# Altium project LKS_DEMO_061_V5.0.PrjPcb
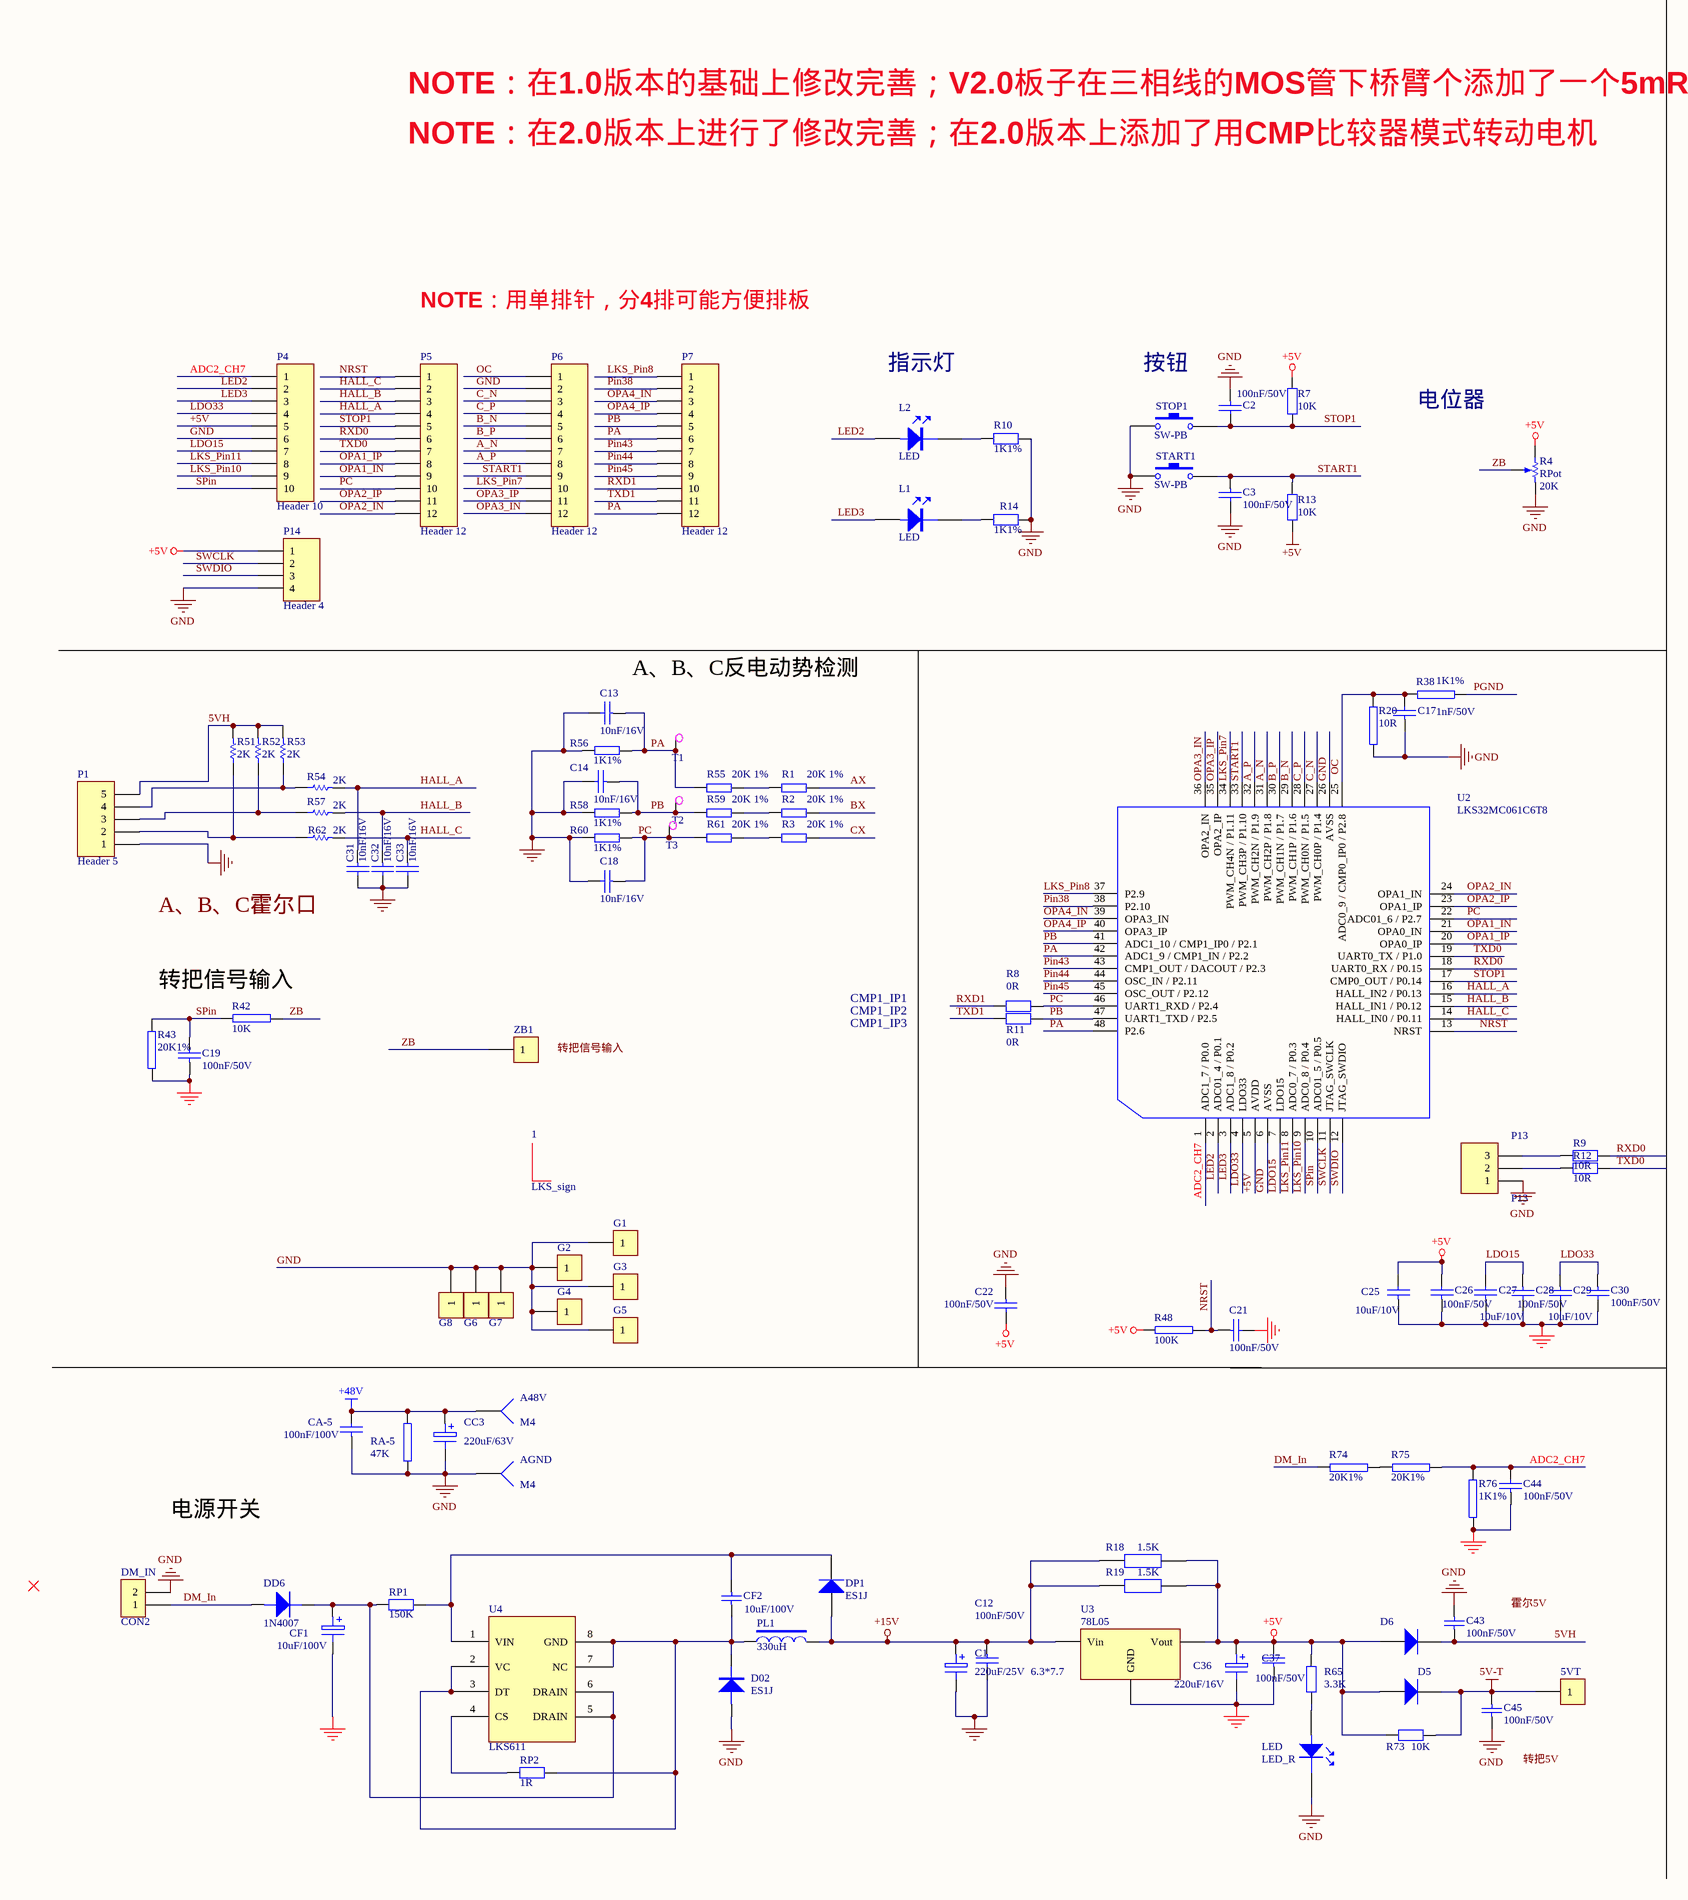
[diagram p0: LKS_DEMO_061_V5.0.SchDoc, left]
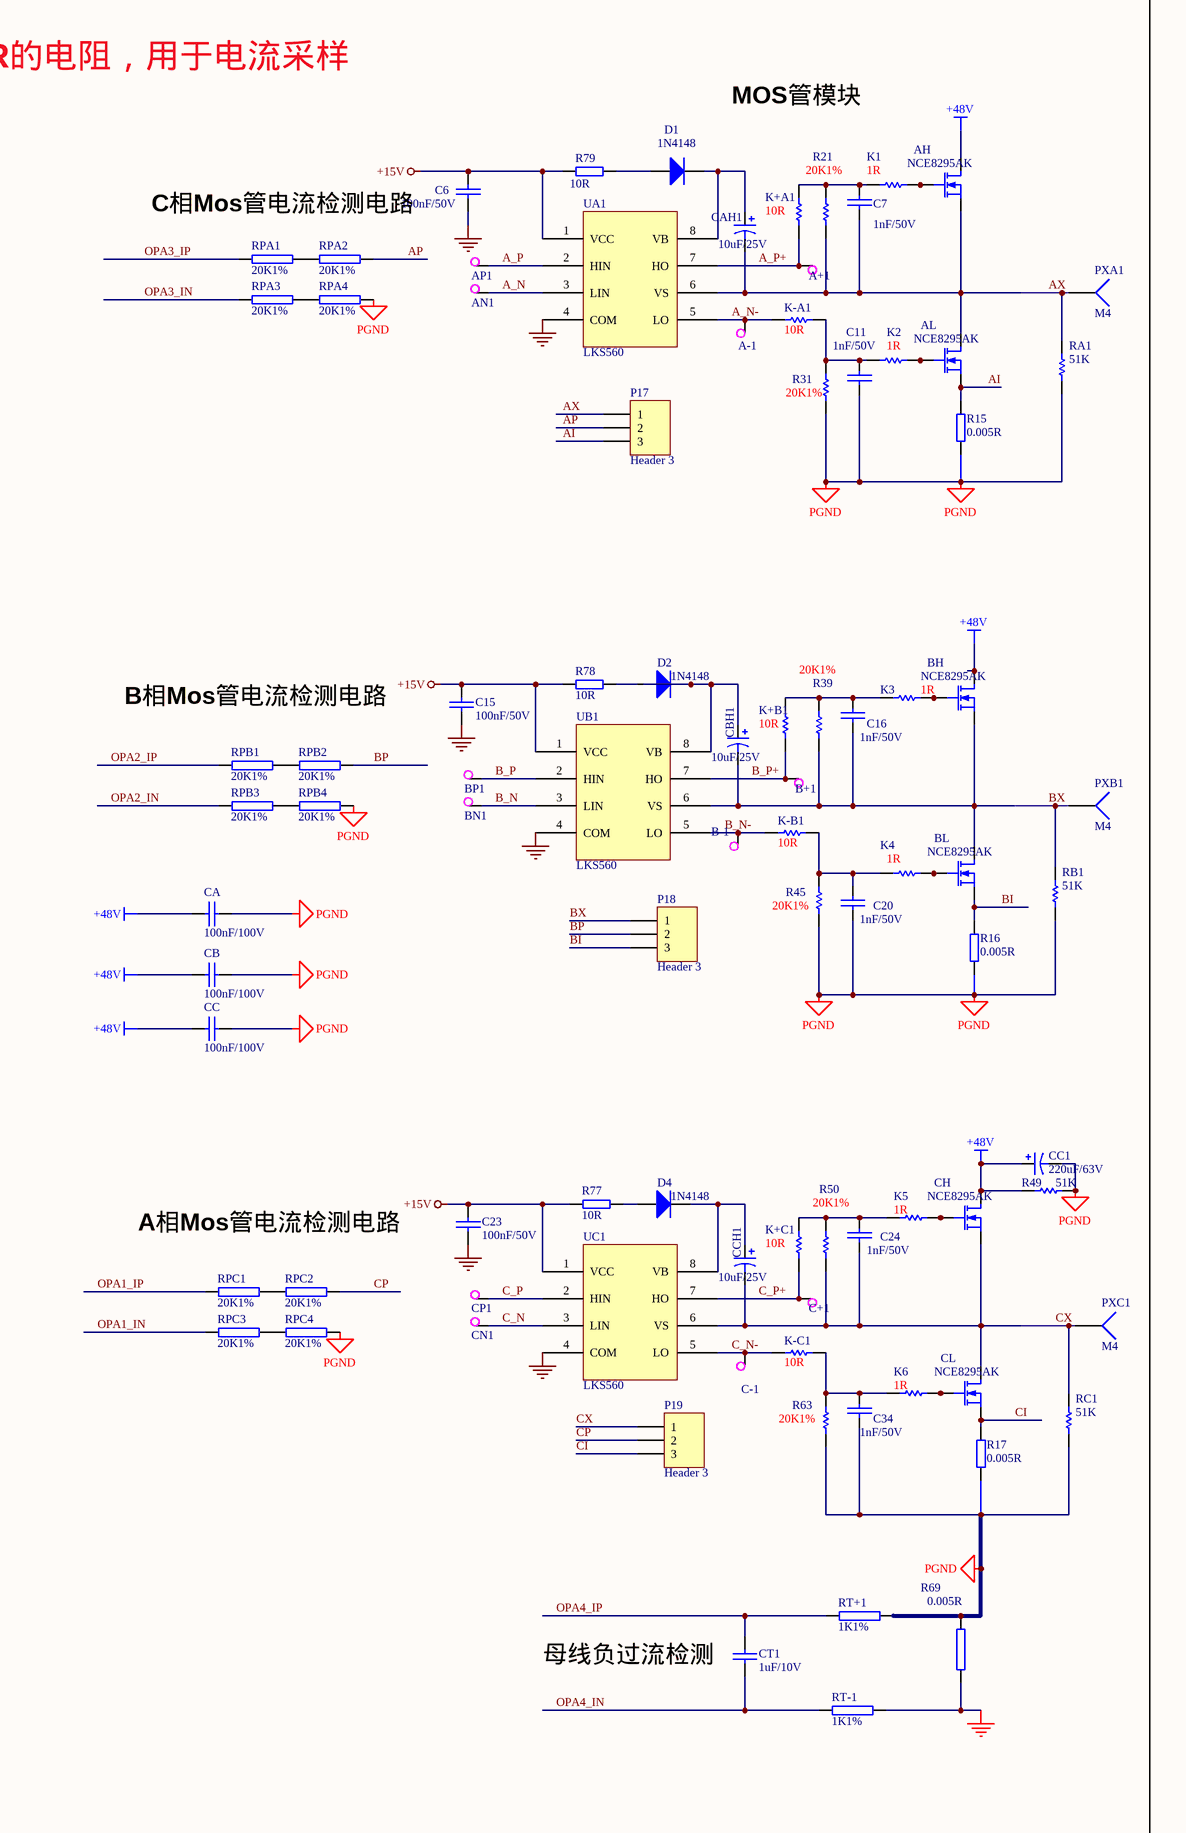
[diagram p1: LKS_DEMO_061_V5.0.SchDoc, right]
1 sheet, 196 parts. Net scope: global (net labels, ports and power ports of the same name join across sheets).
Board file: LKS_DEMO_061_V5.0.PcbDoc

## Sheet LKS_DEMO_061_V5.0.SchDoc
size A2

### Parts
1  LKS_sign  [PCBComponent_1]
5VT  (no value)  [PAD1.2]
A48V  M4  [PCRS250S]
A+1  TestP  [TP-40]  (value not drawn)
A-1  TestP  [TP-40]  (value not drawn)
AGND  M4  [PCRS250S]
AH  NCE8295AK  [TO-252]
AL  NCE8295AK  [TO-252]
AN1  TestP  [TP-40]  (value not drawn)
AP1  TestP  [TP-40]  (value not drawn)
B+1  TestP  [TP-40]  (value not drawn)
B-1  TestP  [TP-40]  (value not drawn)
BH  NCE8295AK  [TO-252]
BL  NCE8295AK  [TO-252]
BN1  TestP  [TP-40]  (value not drawn)
BP1  TestP  [TP-40]  (value not drawn)
C1  220uF/25V  6.3*7.7  [220UF/25V paster8*10]
C2  100nF/50V  [0603C]
C3  100nF/50V  [0603C]
C6  100nF/50V  [0603C]
C7  1nF/50V  [0603C]
C11  1nF/50V  [0603C]
C12  100nF/50V  [0603C]
C13  10nF/16V  [0603C]
C14  10nF/16V  [0603C]
C15  100nF/50V  [0603C]
C16  1nF/50V  [0603C]
C17  1nF/50V  [0603C]
C18  10nF/16V  [0603C]
C19  100nF/50V  [0603C]
C20  1nF/50V  [0603C]
C21  100nF/50V  [0603C]
C22  100nF/50V  [0603C]
C23  100nF/50V  [0603C]
C24  1nF/50V  [0603C]
C25  10uF/10V  [0603C]
C26  100nF/50V  [0603C]
C27  10uF/10V  [0603C]
C28  100nF/50V  [0603C]
C29  10uF/10V  [0603C]
C30  100nF/50V  [0603C]
C31  10nF/16V  [0603C]
C32  10nF/16V  [0603C]
C33  10nF/16V  [0603C]
C34  1nF/50V  [0603C]
C36  220uF/16V  [220UF/16V paster6.3*7.7 - duplicate]
C37  100nF/50V  [0603C]
C43  100nF/50V  [0603C]
C44  100nF/50V  [0603C]
C45  100nF/50V  [0603C]
C+1  TestP  [TP-40]  (value not drawn)
C-1  TestP  [TP-40]  (value not drawn)
CA  100nF/100V  [0805C]
CA-5  100nF/100V  [0805C]
CAH1  10uF/25V  [1206]
CB  100nF/100V  [0805C]
CBH1  10uF/25V  [1206]
CC  100nF/100V  [0805C]
CC1  220uF/63V  [220uF/63V]
CC3  220uF/63V  [220uF/63V]
CCH1  10uF/25V  [1206]
CF1  10uF/100V  [220UF/25V paster6.3*7.7]
CF2  10uF/100V  [1206]
CH  NCE8295AK  [TO-252]
CL  NCE8295AK  [TO-252]
CN1  TestP  [TP-40]  (value not drawn)
CP1  TestP  [TP-40]  (value not drawn)
CT1  1uF/10V  [0603C]
D1  1N4148  [SOD80]
D2  1N4148  [SOD80]
D02  ES1J  [DO-214AC]
D4  1N4148  [SOD80]
D5  1N4007  [D1206]  (value not drawn)
D6  1N4007  [D1206]  (value not drawn)
DD6  1N4007  [DO-214AC]
DM_IN  CON2  [SIP3.96-2]
DP1  ES1J  [DO-214AC]
G1  PAD1.2  [PAD1.2]  (value not drawn)
G2  PAD1.2  [PAD1.2]  (value not drawn)
G3  PAD1.2  [PAD1.2]  (value not drawn)
G4  PAD1.2  [PAD1.2]  (value not drawn)
G5  PAD1.2  [PAD1.2]  (value not drawn)
G6  PAD1.2  [PAD1.2]  (value not drawn)
G7  PAD1.2  [PAD1.2]  (value not drawn)
G8  PAD1.2  [PAD1.2]  (value not drawn)
K1  1R  [0805R]
K2  1R  [0805R]
K3  1R  [0805R]
K4  1R  [0805R]
K5  1R  [0805R]
K6  1R  [0805R]
K+A1  10R  [0805R]
K+B1  10R  [0805R]
K+C1  10R  [0805R]
K-A1  10R  [0805R]
K-B1  10R  [0805R]
K-C1  10R  [0805R]
L1  LED  [SOD323]
L2  LED  [SOD323]
LED  LED_R  [SOD323]
P1  Header 5  [2.54-XH-5A-180]
P4  Header 10  [HDR1X10]
P5  Header 12  [HDR1X12]
P6  Header 12  [HDR1X12]
P7  Header 12  [HDR1X12]
P13  P13  [2.54-XH-3A-180]
P14  Header 4  [HDR1X4]
P17  Header 3  [HDR1X3]
P18  Header 3  [HDR1X3]
P19  Header 3  [HDR1X3]
PL1  330uH  [L_DIP_6*8MM]
PXA1  M4  [PCRS250S]
PXB1  M4  [PCRS250S]
PXC1  M4  [PCRS250S]
R1  20K 1%  [0805R]
R2  20K 1%  [0805R]
R3  20K 1%  [0805R]
R4  RPot  value 20K  [电位器]
R7  10K  [0603R]
R8  0R  [0603R]
R9  10R  [0603R]
R10  1K1%  [0603R]
R11  0R  [0603R]
R12  10R  [0603R]
R13  10K  [0603R]
R14  1K1%  [0603R]
R15  0.005R  [2512]
R16  0.005R  [2512]
R17  0.005R  [2512]
R18  1.5K  [0805R]
R19  1.5K  [0805R]
R20  10R  [0603R]
R21  20K1%  [0603R]
R31  20K1%  [0603R]
R38  1K1%  [0603R]
R39  20K1%  [0603R]
R42  10K  [0603R]
R43  20K1%  [0603R]
R45  20K1%  [0603R]
R48  100K  [0603R]
R49  51K  [0603R]
R50  20K1%  [0603R]
R51  2K  [0603R]
R52  2K  [0603R]
R53  2K  [0603R]
R54  2K  [0603R]
R55  20K 1%  [0805R]
R56  1K1%  [0603R]
R57  2K  [0603R]
R58  1K1%  [0603R]
R59  20K 1%  [0805R]
R60  1K1%  [0603R]
R61  20K 1%  [0805R]
R62  2K  [0603R]
R63  20K1%  [0603R]
R65  3.3K  [0603R]
R69  0.005R  [2512]
R73  10K  [0603R]
R74  20K1%  [0603R]
R75  20K1%  [0603R]
R76  1K1%  [0603R]
R77  10R  [0805r]
R78  10R  [0805r]
R79  10R  [0805r]
RA1  51K  [0603R]
RA-5  47K  [1206]
RB1  51K  [0603R]
RC1  51K  [0603R]
RP1  value 150K  [1206]  (hidden comment: 100K)
RP2  1R  [1206]
RPA1  20K1%  [0603R]
RPA2  20K1%  [0603R]
RPA3  20K1%  [0603R]
RPA4  20K1%  [0603R]
RPB1  20K1%  [0603R]
RPB2  20K1%  [0603R]
RPB3  20K1%  [0603R]
RPB4  20K1%  [0603R]
RPC1  20K1%  [0603R]
RPC2  20K1%  [0603R]
RPC3  20K1%  [0603R]
RPC4  20K1%  [0603R]
RT+1  1K1%  [0603R]
RT-1  1K1%  [0603R]
START1  SW-PB  [SW-PB  12*12]
STOP1  SW-PB  [SW-PB  12*12]
T1  TestP  [TP-40]  (value not drawn)
T2  TestP  [TP-40]  (value not drawn)
T3  TestP  [TP-40]  (value not drawn)
U2  LKS32MC061C6T8  [TQFP48]
U3  78L05  [SOT-89]
U4  LKS611
UA1  LKS560  [SO-8]
UB1  LKS560  [SO-8]
UC1  LKS560  [SO-8]
ZB1  PAD1.2  [PAD1.2]  (value not drawn)

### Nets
5V-T: 5VT.1 C45.2 D5.2(K) R73.2
+5V: C22.2 C25.2 C26.2 C36.1 C37.2 D5.1(A) D6.1(A) P4.5 P14.1 R4.1(TOP) R7.1 R13.2 R18.2 R19.2 R48.2 R65.1 R73.1 U2.5(AVDD) U3.1(Vout)
+15V: C1.1 C6.2 C12.1 C15.2 C23.2 DP1.1(A) PL1.1 R18.1 R19.1 R77.1 R78.1 R79.1 U3.3(Vin) UA1.1(VCC) UB1.1(VCC) UC1.1(VCC)
+48V: A48V.1 AH.2(D) BH.2(D) CA.2 CA-5.2 CB.2 CC.2 CC1.1 CC3.1 CH.2(D) R49.1 RA-5.1
GND: AGND.1 C1.2 C2.1 C3.2 C6.1 C12.2 C13.2 C14.2 C15.1 C17.1 C18.2 C19.1 C21.2 C22.1 C23.1 C25.1 C26.1 C27.1 C28.2 C29.2 C30.2 C31.2 C32.2 C33.2 C36.2 C37.1 C43.1 C44.1 C45.1 CA-5.1 CC3.2 CF1.2 D02.1 DM_IN.2 G1.1 G2.1 G3.1 G4.1 G5.1 G6.1 G7.1 G8.1 LED.2(K) P1.1 P4.6 P6.2 P13.1 P14.4 R4.2(BOT) R10.2 R14.2 R20.1 R43.1 R56.2 R58.2 R60.2 R69.2 R76.1 RA-5.2 RT-1.1 START1.1 STOP1.1 U2.6(AVSS) U2.26(AVSS) U3.2(GND) UA1.4(COM) UB1.4(COM) UC1.4(COM)
PGND: C11.2 C20.2 C34.2 CA.1 CB.1 CC.1 CC1.2 R15.2 R16.1 R17.2 R31.1 R38.2 R45.1 R49.2 R63.1 R69.1 RA1.1 RB1.1 RC1.1 RPA4.1 RPB4.1 RPC4.1 RT+1.1
5VH: C43.2 D6.2(K) P1.5 R51.2 R52.2 R53.2
A_N: AN1.1 P6.7 U2.31(PWM_CH2P_/_P1.8) UA1.3(LIN)
A_N-: A-1.1 K-A1.2 UA1.5(LO)
A_P: AP1.1 P6.8 U2.32(PWM_CH2N_/_P1.9) UA1.2(HIN)
A_P+: A+1.1 K+A1.1 UA1.7(HO)
ADC2_CH7: C44.2 P4.1 R75.2 R76.2 U2.1(ADC1_7_/_P0.0)
AI: AL.3(S) P17.3 R15.1
AP: P17.2 RPA2.1
AX: AH.3(S) AL.2(D) C7.2 CAH1.2 P17.1 PXA1.1 R1.2 R21.1 RA1.2 UA1.6(VS)
B_N: BN1.1 P6.5 U2.29(PWM_CH1P_/_P1.6) UB1.3(LIN)
B_N-: B-1.1 K-B1.2 UB1.5(LO)
B_P: BP1.1 P6.6 U2.30(PWM_CH1N_/_P1.7) UB1.2(HIN)
B_P+: B+1.1 K+B1.1 UB1.7(HO)
BI: BL.3(S) P18.3 R16.2
BP: P18.2 RPB2.1
BX: BH.3(S) BL.2(D) C16.2 CBH1.2 P18.1 PXB1.1 R2.2 R39.1 RB1.2 UB1.6(VS)
C_N: CN1.1 P6.3 U2.27(PWM_CH0P_/_P1.4) UC1.3(LIN)
C_N-: C-1.1 K-C1.2 UC1.5(LO)
C_P: CP1.1 P6.4 U2.28(PWM_CH0N_/_P1.5) UC1.2(HIN)
C_P+: C+1.1 K+C1.1 UC1.7(HO)
CI: CL.3(S) P19.3 R17.1
CP: P19.2 RPC2.1
CX: C24.2 CCH1.2 CH.3(S) CL.2(D) P19.1 PXC1.1 R3.2 R50.1 RC1.2 UC1.6(VS)
DM_In: DD6.1 DM_IN.1 R74.1
HALL_A: C31.1 P5.4 R54.2 U2.16(HALL_IN2_/_P0.13)
HALL_B: C32.1 P5.3 R57.2 U2.15(HALL_IN1_/_P0.12)
HALL_C: C33.1 P5.2 R62.2 U2.14(HALL_IN0_/_P0.11)
LDO15: C27.2 C28.1 P4.7 U2.7(LDO15)
LDO33: C29.1 C30.1 P4.4 U2.4(LDO33)
LED2: L2.1(A) P4.2 U2.2(ADC01_4_/_P0.1)
LED3: L1.1(A) P4.3 U2.3(ADC1_8_/_P0.2)
LKS_Pin7: P6.10 U2.34(PWM_CH4N_/_P1.11)
LKS_Pin8: P7.1 U2.37(P2.9)
LKS_Pin10: P4.9 U2.9(ADC0_8_/_P0.4)
LKS_Pin11: P4.8 U2.8(ADC0_7_/_P0.3)
NRST: C21.1 P5.1 R48.1 U2.13(NRST)
OC: C17.2 P6.1 R20.2 R38.1 U2.25(ADC0_9_/_CMP0_IP0_/_P2.8)
OPA1_IN: P5.9 RPC3.2 U2.21(OPA0_IN)
OPA1_IP: P5.8 RPC1.2 U2.20(OPA0_IP)
OPA2_IN: P5.12 RPB3.2 U2.24(OPA1_IN)
OPA2_IP: P5.11 RPB1.2 U2.23(OPA1_IP)
OPA3_IN: P6.12 RPA3.2 U2.36(OPA2_IN)
OPA3_IP: P6.11 RPA1.2 U2.35(OPA2_IP)
OPA4_IN: CT1.2 P7.3 RT-1.2 U2.39(OPA3_IN)
OPA4_IP: CT1.1 P7.4 RT+1.2 U2.40(OPA3_IP)
PA: C13.1 P7.6 P7.12 R55.1 R56.1 T1.1 U2.42(ADC1_9_/_CMP1_IN_/_P2.2) U2.48(P2.6)
PB: C14.1 P7.5 R11.2 R58.1 R59.1 T2.1 U2.41(ADC1_10_/_CMP1_IP0_/_P2.1) U2.47(UART1_TXD_/_P2.5)
PC: C18.1 P5.10 R8.1 R60.1 R61.1 T3.1 U2.22(ADC01_6_/_P2.7) U2.46(UART1_RXD_/_P2.4)
Pin38: P7.2 U2.38(P2.10)
Pin43: P7.7 U2.43(CMP1_OUT_/_DACOUT_/_P2.3)
Pin44: P7.8 U2.44(OSC_IN_/_P2.11)
Pin45: P7.9 U2.45(OSC_OUT_/_P2.12)
RXD0: P5.6 R9.1 U2.18(UART0_RX_/_P0.15)
RXD1: P7.10 R8.2
SPin: C19.2 P4.10 R42.2 R43.2 U2.10(ADC01_5_/_P0.5)
START1: C3.1 P6.9 R13.1 START1.2 U2.33(PWM_CH3P_/_P1.10)
STOP1: C2.2 P5.5 R7.2 STOP1.2 U2.17(CMP0_OUT_/_P0.14)
SWCLK: P14.2 U2.11(JTAG_SWCLK)
SWDIO: P14.3 U2.12(JTAG_SWDIO)
TXD0: P5.7 R12.2 U2.19(UART0_TX_/_P1.0)
TXD1: P7.11 R11.1
ZB: R4.3(TAP) R42.1 ZB1.1
NetAH_1: AH.1(G) K1.2
NetAL_1: AL.1(G) K2.2
NetBH_1: BH.1(G) K3.2
NetBL_1: BL.1(G) K4.2
NetC7_1: C7.1 K1.1 K+A1.2 R21.2
NetC11_1: C11.1 K2.1 K-A1.1 R31.2
NetC16_1: C16.1 K3.1 K+B1.2 R39.2
NetC20_1: C20.1 K4.1 K-B1.1 R45.2
NetC24_1: C24.1 K5.1 K+C1.2 R50.2
NetC34_1: C34.1 K6.1 K-C1.1 R63.2
NetCAH1_1: CAH1.1 D1.2(K) UA1.8(VB)
NetCBH1_1: CBH1.1 D2.2(K) UB1.8(VB)
NetCCH1_1: CCH1.1 D4.2(K) UC1.8(VB)
NetCF1_1: CF1.1 DD6.2 RP1.2 U4.5(DRAIN) U4.6(DRAIN)
NetCF2_1: CF2.1 DP1.2(K) RP1.1 U4.1(VIN)
NetCF2_2: CF2.2 D02.2 PL1.2 RP2.2 U4.2(VC) U4.3(DT) U4.7(NC) U4.8(GND)
NetCH_1: CH.1(G) K5.2
NetCL_1: CL.1(G) K6.2
NetD1_1: D1.1(A) R79.2
NetD2_1: D2.1(A) R78.2
NetD4_1: D4.1(A) R77.2
NetL1_2: L1.2(K) R14.1
NetL2_2: L2.2(K) R10.1
NetLED_1: LED.1(A) R65.2
NetP1_2: P1.2 R51.1 R62.1
NetP1_3: P1.3 R52.1 R57.1
NetP1_4: P1.4 R53.1 R54.1
NetP13_2: P13.2 R12.1
NetP13_3: P13.3 R9.2
NetR1_1: R1.1 R55.2
NetR2_1: R2.1 R59.2
NetR3_1: R3.1 R61.2
NetR74_2: R74.2 R75.1
NetRP2_1: RP2.1 U4.4(CS)
NetRPA1_1: RPA1.1 RPA2.2
NetRPA3_1: RPA3.1 RPA4.2
NetRPB1_1: RPB1.1 RPB2.2
NetRPB3_1: RPB3.1 RPB4.2
NetRPC1_1: RPC1.1 RPC2.2
NetRPC3_1: RPC3.1 RPC4.2

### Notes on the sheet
- NOTE：在1.0版本的基础上修改完善；V2.0板子在三相线的MOS管下桥臂个添加了一个5mR的电阻，用于电流采样
- MOS管模块
- NOTE：在2.0版本上进行了修改完善；在2.0版本上添加了用CMP比较器模式转动电机
- C相Mos管电流检测电路
- NOTE：用单排针，分4排可能方便排板
- 指示灯
- 按钮
- 电位器
- B相Mos管电流检测电路
- 转把信号输入
- CMP1_IP1
- CMP1_IP2
- CMP1_IP3
- A相Mos管电流检测电路
- 母线负过流检测
- Labels drawn without touching a wire or pin: A、B、C反电动势检测, A、B、C霍尔口, 电源开关, 转把5V, 转把信号输入, 霍尔5V

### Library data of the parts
5VT G1-G8 ZB1 = CON1: Connector
A48V AGND PXA1 PXB1 PXC1 = Socket
AH AL BH BL CH CL = MOS
C1 C36 CC3 CF1 = CD: Electrolytic Capacitor
C2 C3 C7 C11-C14 C16 C18 C20 C24 C31-C34 CA CB CC = CAP: Capacitor
C6 C15 C17 C19 C21-C23 C25-C30 C37 C44 CA-5 CT1 = C: Capacitor
C43 C45 = Cap: Capacitor; Value: 104
CAH1 CBH1 CCH1 = Cap Pol1: Polarized Capacitor (Radial); Value: 47uF/50V
CC1 = Cap Pol1: Polarized Capacitor (Radial); Value: 1uF
CF2 = Cap: Capacitor
D1 D2 D4 = Diode: Default Diode
D02 DD6 = D: Diode
D5 D6 DP1 = Diode 1N4007: 1 Amp General Purpose Rectifier
DM_IN = CON2: Connector
K1-K6 K+A1 K+B1 K+C1 K-A1 K-B1 K-C1 R21 R31 R39 R45 R50 R63 = Res1: Resistor; Value: 150
LED = LED
P1 = Header 5: Header, 5-Pin
P4 = Header 10: Header, 10-Pin
P5-P7 = Header 12: Header, 12-Pin
P13 P17-P19 = Header 3: Header, 3-Pin
P14 = Header 4: Header, 4-Pin
PL1 = L
R1-R3 R55 R56 R58-R61 = RES/1
R4 = RPot: Potentiometer; Sim Note: Enter the Resistance value and the set point into parameter fields.; Set Position: 0.5
R7-R9 R13 R73 RP1 RP2 = Res2: Resistor
R10 R14 = Res2: Resistor; Value: 10K
R11 R12 = Res2: Resistor; Value: 100R
R15-R17 R77-R79 = RES2短
R18 R19 = R-2W: 1W或2W功率电阻器
R20 R38 R42 R43 R48 R69 R74-R76 RA-5 RPA1-RPA4 RPB1-RPB4 RPC1-RPC4 RT+1 RT-1 = R
R49 = Res1: Resistor; Value: 47K
R51-R54 R57 R62 = Res1: Resistor; Value: 2.2K
R65 = Res2: Resistor; Value: 510R
RA1 RB1 RC1 = Res1: Resistor; Value: 10K
START1 STOP1 = SW-PB: Switch
U2 = LKS48
U3 = VOL-78
UA1 UB1 UC1 = IRS2003S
